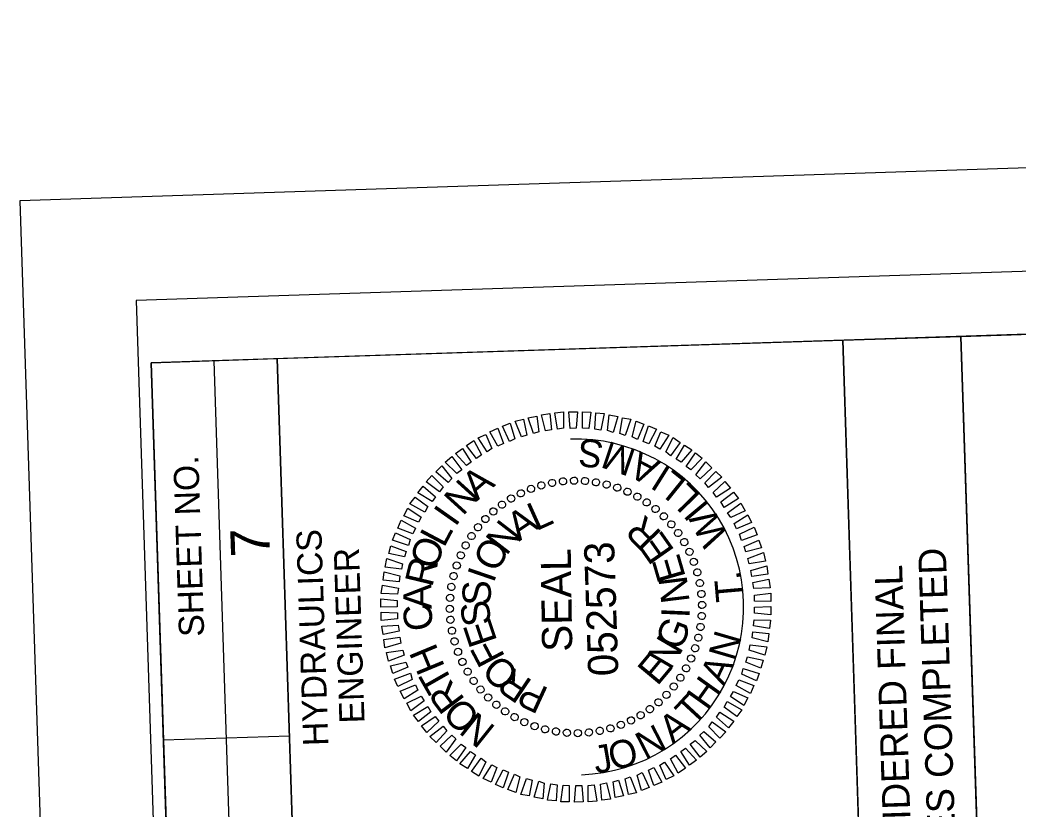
# Model space of a CAD drawing. Extents: x 1627314 to 1628469, y 762309 to 764212.
# Drawn here: x 1627314.2 to 1627512.6, y 763887.6 to 764044.4 of the extents above; entities that cross this region are included whole.
import ezdxf

# ---------------------------------------------------------------- set-up
doc = ezdxf.new("R2010")
doc.units = 0
for name, color, linetype in [('Old_Level_58', 7, 'Continuous'), ('Scratch_Level_0', 7, 'Continuous'), ('Sheet Data Field CELL', 7, 'Continuous'), ('Sheet Plot Border Inside CELL', 7, 'Continuous'), ('Sheet Plot Border Outside CELL', 7, 'Continuous'), ('Sheet Professional Seal CELL', 7, 'Continuous'), ('Sheet Profile CELL', 7, 'Continuous'), ('Sheet Profile Grid Major CELL', 7, 'Continuous'), ('Sheet Profile Grid Minor CELL', 7, 'Continuous'), ('Sheet Sticker Exception Certification CELL', 7, 'Continuous')]:
    doc.layers.add(name, color=color, linetype=linetype)

msp = doc.modelspace()

# ---------------------------------------------------------------- linework, layer by layer
at = {"layer": 'Old_Level_58'}
msp.add_lwpolyline([(1627507.79, 763781.55), (1627501.25, 763981.49), (1627565.16, 763983.58), (1627571.7, 763783.64)], close=True, dxfattribs=at)
at = {"layer": 'Scratch_Level_0'}
msp.add_arc((1627424.73, 763927.73), 33.36, 271.8735, 91.8735, dxfattribs=at)
at = {"layer": 'Sheet Plot Border Inside CELL'}
msp.add_lwpolyline([(1628446.34, 762357.53), (1628391.86, 764023.14), (1627337.33, 763988.65), (1627391.81, 762323.04)], close=True, dxfattribs=at)
at = {"layer": 'Sheet Plot Border Outside CELL'}
msp.add_lwpolyline([(1628469.21, 762345.27), (1628413.63, 764044.37), (1627314.22, 764008.4), (1627369.79, 762309.31)], close=True, dxfattribs=at)
at = {"layer": 'Sheet Professional Seal CELL'}
for p, q in [((1627417.84, 763951.87), (1627417.84, 763951.87)), ((1627420.03, 763952.34), (1627420.03, 763952.34)), ((1627422.17, 763952.71), (1627422.17, 763952.71)), ((1627424.36, 763952.83), (1627424.36, 763952.83)), ((1627426.57, 763952.75), (1627426.57, 763952.75)), ((1627428.73, 763952.48), (1627428.73, 763952.48)), ((1627430.84, 763952.09), (1627430.84, 763952.09)), ((1627432.96, 763951.46), (1627432.96, 763951.46)), ((1627413.79, 763950.34), (1627413.79, 763950.34)), ((1627415.76, 763951.2), (1627415.76, 763951.2)), ((1627434.99, 763950.63), (1627434.99, 763950.63)), ((1627436.97, 763949.69), (1627436.97, 763949.69)), ((1627410.01, 763948.06), (1627410.01, 763948.06)), ((1627411.87, 763949.27), (1627411.87, 763949.27)), ((1627438.81, 763948.5), (1627438.81, 763948.5)), ((1627408.3, 763946.75), (1627408.3, 763946.75)), ((1627440.61, 763947.21), (1627440.61, 763947.21)), ((1627442.2, 763945.76), (1627442.2, 763945.76)), ((1627405.26, 763943.6), (1627405.26, 763943.6)), ((1627406.7, 763945.2), (1627406.7, 763945.2)), ((1627443.76, 763944.16), (1627443.76, 763944.16)), ((1627403.96, 763941.81), (1627403.96, 763941.81)), ((1627445.06, 763942.45), (1627445.06, 763942.45)), ((1627402.77, 763939.97), (1627402.77, 763939.97)), ((1627446.28, 763940.59), (1627446.28, 763940.59)), ((1627401.84, 763937.99), (1627401.84, 763937.99)), ((1627447.34, 763938.68), (1627447.34, 763938.68)), ((1627401, 763935.96), (1627401, 763935.96)), ((1627448.2, 763936.7), (1627448.2, 763936.7)), ((1627400.37, 763933.84), (1627400.37, 763933.84)), ((1627448.87, 763934.62), (1627448.87, 763934.62)), ((1627399.99, 763931.72), (1627399.99, 763931.72)), ((1627449.34, 763932.44), (1627449.34, 763932.44)), ((1627449.71, 763930.3), (1627449.71, 763930.3)), ((1627399.71, 763929.56), (1627399.71, 763929.56)), ((1627424.73, 763927.73), (1627424.73, 763927.73)), ((1627449.84, 763928.1), (1627449.84, 763928.1)), ((1627399.63, 763927.36), (1627399.63, 763927.36)), ((1627449.76, 763925.9), (1627449.76, 763925.9)), ((1627399.76, 763925.16), (1627399.76, 763925.16)), ((1627449.48, 763923.74), (1627449.48, 763923.74)), ((1627400.13, 763923.02), (1627400.13, 763923.02)), ((1627400.6, 763920.84), (1627400.6, 763920.84)), ((1627449.1, 763921.62), (1627449.1, 763921.62)), ((1627401.27, 763918.76), (1627401.27, 763918.76)), ((1627448.47, 763919.5), (1627448.47, 763919.5)), ((1627402.13, 763916.79), (1627402.13, 763916.79)), ((1627447.63, 763917.47), (1627447.63, 763917.47)), ((1627403.19, 763914.87), (1627403.19, 763914.87)), ((1627446.7, 763915.49), (1627446.7, 763915.49)), ((1627404.4, 763913.01), (1627404.4, 763913.01)), ((1627444.21, 763911.86), (1627444.21, 763911.86)), ((1627445.51, 763913.65), (1627445.51, 763913.65)), ((1627405.71, 763911.3), (1627405.71, 763911.3)), ((1627442.77, 763910.26), (1627442.77, 763910.26)), ((1627407.26, 763909.7), (1627407.26, 763909.7)), ((1627408.86, 763908.25), (1627408.86, 763908.25)), ((1627441.17, 763908.71), (1627441.17, 763908.71)), ((1627410.66, 763906.96), (1627410.66, 763906.96)), ((1627437.6, 763906.19), (1627437.6, 763906.19)), ((1627439.46, 763907.4), (1627439.46, 763907.4)), ((1627412.5, 763905.77), (1627412.5, 763905.77)), ((1627414.48, 763904.83), (1627414.48, 763904.83)), ((1627416.51, 763904), (1627416.51, 763904)), ((1627433.71, 763904.26), (1627433.71, 763904.26)), ((1627435.68, 763905.13), (1627435.68, 763905.13)), ((1627418.63, 763903.37), (1627418.63, 763903.37)), ((1627420.74, 763902.99), (1627420.74, 763902.99)), ((1627422.9, 763902.71), (1627422.9, 763902.71)), ((1627425.11, 763902.63), (1627425.11, 763902.63)), ((1627427.3, 763902.75), (1627427.3, 763902.75)), ((1627429.44, 763903.12), (1627429.44, 763903.12)), ((1627431.63, 763903.59), (1627431.63, 763903.59))]:
    msp.add_line(p, q, dxfattribs=at)
for points in [[(1627416.3, 763962.17), (1627415.25, 763965.29), (1627416.94, 763965.65), (1627417.34, 763962.51)], [(1627418.69, 763962.7), (1627417.88, 763965.93), (1627419.58, 763966.13), (1627419.88, 763962.94)], [(1627421.08, 763963.08), (1627420.57, 763966.32), (1627422.27, 763966.47), (1627422.27, 763963.22)], [(1627423.57, 763963.21), (1627423.32, 763966.46), (1627425.02, 763966.51), (1627424.77, 763963.25)], [(1627426.07, 763963.24), (1627426.07, 763966.5), (1627427.72, 763966.45), (1627427.28, 763963.18)], [(1627428.48, 763963.07), (1627428.68, 763966.28), (1627430.38, 763966.14), (1627429.69, 763962.86)], [(1627431.04, 763962.76), (1627431.34, 763965.87), (1627433.05, 763965.57), (1627432.11, 763962.39)], [(1627433.46, 763962.19), (1627434.01, 763965.31), (1627435.67, 763965.01), (1627434.53, 763961.82)], [(1627411.55, 763960.62), (1627410.15, 763963.62), (1627411.68, 763964.22), (1627412.59, 763961.15)], [(1627413.92, 763961.5), (1627412.67, 763964.66), (1627414.31, 763965.01), (1627414.96, 763961.88)], [(1627435.89, 763961.51), (1627436.68, 763964.64), (1627438.25, 763964.04), (1627436.95, 763961)], [(1627438.12, 763960.59), (1627439.17, 763963.72), (1627440.74, 763963.02), (1627439.23, 763960.12)], [(1627407.12, 763958.57), (1627405.28, 763961.31), (1627406.8, 763962.01), (1627408.05, 763959.2)], [(1627409.23, 763959.64), (1627407.64, 763962.54), (1627409.22, 763963.24), (1627410.32, 763960.18)], [(1627440.45, 763959.66), (1627441.61, 763962.55), (1627443.18, 763961.85), (1627441.42, 763959.09)], [(1627442.64, 763958.53), (1627444.04, 763961.38), (1627445.48, 763960.43), (1627443.56, 763957.76)], [(1627404.96, 763957.2), (1627402.97, 763959.79), (1627404.44, 763960.79), (1627405.94, 763957.93)], [(1627444.69, 763957.1), (1627446.3, 763959.85), (1627447.78, 763958.95), (1627445.66, 763956.48)], [(1627401.05, 763954.27), (1627398.73, 763956.5), (1627400.05, 763957.59), (1627402.03, 763955)], [(1627402.95, 763955.83), (1627400.78, 763958.21), (1627402.19, 763959.21), (1627403.88, 763956.47)], [(1627446.63, 763955.66), (1627448.5, 763958.32), (1627449.83, 763957.27), (1627447.56, 763954.99)], [(1627399.31, 763952.46), (1627396.89, 763954.54), (1627398.05, 763955.77), (1627400.09, 763953.24)], [(1627448.59, 763953.98), (1627450.55, 763956.59), (1627451.75, 763955.38), (1627449.41, 763953.2)], [(1627397.62, 763950.61), (1627394.96, 763952.57), (1627396.12, 763953.81), (1627398.34, 763951.58)], [(1627450.39, 763952.38), (1627452.52, 763954.65), (1627453.76, 763953.49), (1627451.12, 763951.46)], [(1627396.14, 763948.66), (1627393.33, 763950.42), (1627394.38, 763951.75), (1627396.8, 763949.63)], [(1627452.01, 763950.44), (1627454.34, 763952.66), (1627455.43, 763951.35), (1627452.69, 763949.51)], [(1627394.7, 763946.56), (1627391.75, 763948.21), (1627392.75, 763949.55), (1627395.27, 763947.68)], [(1627453.57, 763948.59), (1627456.06, 763950.52), (1627457.05, 763949.25), (1627454.2, 763947.51)], [(1627454.89, 763946.43), (1627457.53, 763948.36), (1627458.38, 763946.84), (1627455.52, 763945.5)], [(1627393.42, 763944.57), (1627390.52, 763945.82), (1627391.33, 763947.35), (1627393.99, 763945.54)], [(1627456.16, 763944.32), (1627458.91, 763946.01), (1627459.66, 763944.48), (1627456.64, 763943.23)], [(1627392.34, 763942.23), (1627389.35, 763943.38), (1627390, 763944.96), (1627392.86, 763943.35)], [(1627457.28, 763942.15), (1627460.14, 763943.55), (1627460.79, 763942.07), (1627457.62, 763940.91)], [(1627391.47, 763939.95), (1627388.28, 763941), (1627388.84, 763942.42), (1627391.78, 763941.11)], [(1627390.64, 763937.67), (1627387.52, 763938.32), (1627387.97, 763939.89), (1627390.96, 763938.73)], [(1627458.16, 763939.73), (1627461.12, 763940.98), (1627461.62, 763939.44), (1627458.54, 763938.69)], [(1627458.89, 763937.35), (1627462, 763938.51), (1627462.41, 763936.82), (1627459.17, 763936.31)], [(1627390.07, 763935.25), (1627386.81, 763935.65), (1627387.15, 763937.36), (1627390.29, 763936.31)], [(1627459.52, 763934.97), (1627462.69, 763935.88), (1627462.89, 763934.23), (1627459.71, 763933.78)], [(1627389.6, 763932.69), (1627386.39, 763933.03), (1627386.59, 763934.69), (1627389.71, 763933.89)], [(1627389.28, 763930.27), (1627386.03, 763930.37), (1627386.27, 763932.03), (1627389.44, 763931.48)], [(1627459.89, 763932.58), (1627463.07, 763933.24), (1627463.33, 763931.55), (1627460.08, 763931.39)], [(1627460.23, 763930.09), (1627463.47, 763930.45), (1627463.47, 763928.8), (1627460.22, 763928.89)], [(1627389.21, 763927.77), (1627385.97, 763927.66), (1627385.96, 763929.31), (1627389.22, 763928.97)], [(1627460.25, 763927.69), (1627463.5, 763927.8), (1627463.51, 763926.15), (1627460.24, 763926.49)], [(1627389.24, 763925.37), (1627386, 763925.01), (1627386, 763926.66), (1627389.25, 763926.57)], [(1627389.57, 763922.88), (1627386.39, 763922.23), (1627386.14, 763923.92), (1627389.39, 763924.07)], [(1627460.19, 763925.19), (1627463.44, 763925.1), (1627463.2, 763923.44), (1627460.03, 763923.98)], [(1627389.95, 763920.49), (1627386.78, 763919.59), (1627386.58, 763921.23), (1627389.76, 763921.69)], [(1627459.87, 763922.78), (1627463.08, 763922.43), (1627462.88, 763920.78), (1627459.75, 763921.57)], [(1627459.4, 763920.21), (1627462.66, 763919.82), (1627462.32, 763918.11), (1627459.18, 763919.15)], [(1627390.58, 763918.11), (1627387.47, 763916.96), (1627387.06, 763918.65), (1627390.3, 763919.15)], [(1627458.83, 763917.79), (1627461.95, 763917.14), (1627461.5, 763915.58), (1627458.51, 763916.73)], [(1627391.31, 763915.73), (1627388.35, 763914.49), (1627387.85, 763916.02), (1627390.92, 763916.77)], [(1627392.19, 763913.31), (1627389.33, 763911.92), (1627388.68, 763913.4), (1627391.85, 763914.55)], [(1627458, 763915.51), (1627461.19, 763914.47), (1627460.63, 763913.05), (1627457.69, 763914.35)], [(1627393.31, 763911.15), (1627390.56, 763909.45), (1627389.81, 763910.98), (1627392.82, 763912.23)], [(1627457.13, 763913.23), (1627460.12, 763912.08), (1627459.47, 763910.51), (1627456.61, 763912.12)], [(1627394.58, 763909.04), (1627391.94, 763907.1), (1627391.09, 763908.62), (1627393.95, 763909.97)], [(1627456.05, 763910.9), (1627458.94, 763909.64), (1627458.14, 763908.11), (1627455.48, 763909.93)], [(1627395.9, 763906.88), (1627393.41, 763904.95), (1627392.42, 763906.21), (1627395.27, 763907.96)], [(1627454.77, 763908.9), (1627457.72, 763907.25), (1627456.71, 763905.92), (1627454.2, 763907.78)], [(1627397.46, 763905.03), (1627395.13, 763902.8), (1627394.04, 763904.12), (1627396.78, 763905.96)], [(1627453.33, 763906.81), (1627456.14, 763905.05), (1627455.09, 763903.71), (1627452.67, 763905.83)], [(1627399.08, 763903.08), (1627396.95, 763900.81), (1627395.71, 763901.97), (1627398.35, 763904.01)], [(1627451.85, 763904.86), (1627454.51, 763902.89), (1627453.35, 763901.65), (1627451.13, 763903.88)], [(1627400.88, 763901.49), (1627398.91, 763898.87), (1627397.72, 763900.08), (1627400.05, 763902.26)], [(1627450.16, 763903), (1627452.58, 763900.93), (1627451.42, 763899.69), (1627449.38, 763902.22)], [(1627402.84, 763899.8), (1627400.97, 763897.14), (1627399.64, 763898.2), (1627401.91, 763900.47)], [(1627448.41, 763901.19), (1627450.74, 763898.97), (1627449.42, 763897.87), (1627447.44, 763900.46)], [(1627404.78, 763898.36), (1627403.17, 763895.61), (1627401.69, 763896.51), (1627403.81, 763898.98)], [(1627444.51, 763898.26), (1627446.49, 763895.68), (1627445.03, 763894.68), (1627443.53, 763897.53)], [(1627446.51, 763899.63), (1627448.69, 763897.25), (1627447.28, 763896.25), (1627445.59, 763899)], [(1627406.83, 763896.93), (1627405.42, 763894.08), (1627403.99, 763895.04), (1627405.91, 763897.7)], [(1627409.02, 763895.8), (1627407.86, 763892.91), (1627406.29, 763893.61), (1627408.05, 763896.37)], [(1627442.35, 763896.89), (1627444.19, 763894.15), (1627442.66, 763893.45), (1627441.42, 763896.26)], [(1627411.35, 763894.88), (1627410.3, 763891.74), (1627408.73, 763892.44), (1627410.24, 763895.34)], [(1627413.58, 763893.95), (1627412.78, 763890.82), (1627411.21, 763891.42), (1627412.52, 763894.46)], [(1627435.54, 763893.97), (1627436.8, 763890.81), (1627435.16, 763890.45), (1627434.51, 763893.58)], [(1627437.92, 763894.85), (1627439.32, 763891.84), (1627437.78, 763891.24), (1627436.88, 763894.31)], [(1627440.24, 763895.82), (1627441.83, 763892.92), (1627440.25, 763892.22), (1627439.15, 763895.29)], [(1627416.01, 763893.28), (1627415.46, 763890.16), (1627413.8, 763890.45), (1627414.94, 763893.64)], [(1627418.43, 763892.71), (1627418.13, 763889.6), (1627416.42, 763889.89), (1627417.36, 763893.07)], [(1627420.99, 763892.39), (1627420.79, 763889.18), (1627419.09, 763889.33), (1627419.78, 763892.6)], [(1627423.39, 763892.22), (1627423.4, 763888.97), (1627421.75, 763889.01), (1627422.19, 763892.28)], [(1627425.9, 763892.25), (1627426.15, 763889.01), (1627424.45, 763888.95), (1627424.7, 763892.21)], [(1627428.39, 763892.38), (1627428.9, 763889.15), (1627427.2, 763888.99), (1627427.2, 763892.24)], [(1627430.78, 763892.76), (1627431.59, 763889.54), (1627429.89, 763889.33), (1627429.59, 763892.52)], [(1627433.17, 763893.29), (1627434.22, 763890.17), (1627432.53, 763889.82), (1627432.13, 763892.95)]]:
    msp.add_lwpolyline(points, close=True, dxfattribs=at)
for centre, major_axis in [((1627422.17, 763952.68), (-0.074, 0.716)), ((1627424.35, 763952.81), (-0.011, 0.72)), ((1627426.54, 763952.75), (0.052, 0.718)), ((1627415.8, 763951.17), (-0.257, 0.673)), ((1627417.87, 763951.86), (-0.197, 0.693)), ((1627420, 763952.36), (-0.136, 0.707)), ((1627428.71, 763952.49), (0.114, 0.711)), ((1627430.86, 763952.05), (0.176, 0.698)), ((1627432.95, 763951.43), (0.236, 0.68)), ((1627434.99, 763950.62), (0.294, 0.657)), ((1627411.86, 763949.26), (-0.369, 0.618)), ((1627413.79, 763950.3), (-0.314, 0.648)), ((1627436.94, 763949.64), (0.35, 0.629)), ((1627408.32, 763946.7), (-0.471, 0.544)), ((1627410.04, 763948.05), (-0.422, 0.583)), ((1627438.8, 763948.49), (0.404, 0.596)), ((1627440.56, 763947.19), (0.454, 0.559)), ((1627406.73, 763945.19), (-0.517, 0.501)), ((1627442.2, 763945.73), (0.501, 0.517)), ((1627405.28, 763943.56), (-0.559, 0.454)), ((1627443.7, 763944.14), (0.544, 0.471)), ((1627403.97, 763941.8), (-0.596, 0.404)), ((1627445.06, 763942.43), (0.583, 0.422)), ((1627402.83, 763939.94), (-0.629, 0.35)), ((1627446.26, 763940.6), (0.618, 0.369)), ((1627401.85, 763937.98), (-0.657, 0.294)), ((1627447.3, 763938.68), (0.648, 0.314)), ((1627401.04, 763935.95), (-0.68, 0.236)), ((1627448.17, 763936.67), (0.673, 0.257)), ((1627400.41, 763933.85), (-0.698, 0.176)), ((1627448.86, 763934.59), (0.693, 0.197)), ((1627399.97, 763931.71), (-0.711, 0.114)), ((1627449.36, 763932.46), (0.707, 0.136)), ((1627399.72, 763929.54), (-0.718, 0.052)), ((1627449.68, 763930.3), (0.716, 0.074)), ((1627399.66, 763927.35), (-0.72, -0.011)), ((1627449.81, 763928.11), (0.72, 0.011)), ((1627399.79, 763925.17), (-0.716, -0.074)), ((1627449.75, 763925.93), (0.718, -0.052)), ((1627400.1, 763923), (-0.707, -0.136)), ((1627449.5, 763923.75), (0.711, -0.114)), ((1627400.61, 763920.87), (-0.693, -0.197)), ((1627449.06, 763921.61), (0.698, -0.176)), ((1627448.43, 763919.51), (0.68, -0.236)), ((1627401.3, 763918.8), (-0.673, -0.257)), ((1627447.62, 763917.48), (0.657, -0.294)), ((1627402.17, 763916.79), (-0.648, -0.314)), ((1627446.64, 763915.52), (0.629, -0.35)), ((1627403.21, 763914.86), (-0.618, -0.369)), ((1627404.41, 763913.03), (-0.583, -0.422)), ((1627445.5, 763913.66), (0.596, -0.404)), ((1627405.77, 763911.32), (-0.544, -0.471)), ((1627444.19, 763911.91), (0.559, -0.454)), ((1627407.27, 763909.73), (-0.501, -0.517)), ((1627442.74, 763910.27), (0.517, -0.501)), ((1627408.91, 763908.28), (-0.454, -0.559)), ((1627410.66, 763906.97), (-0.404, -0.596)), ((1627439.43, 763907.41), (0.422, -0.583)), ((1627441.15, 763908.77), (0.471, -0.544)), ((1627412.53, 763905.82), (-0.35, -0.629)), ((1627435.68, 763905.17), (0.314, -0.648)), ((1627437.6, 763906.21), (0.369, -0.618)), ((1627414.48, 763904.84), (-0.294, -0.657)), ((1627416.52, 763904.04), (-0.236, -0.68)), ((1627418.61, 763903.41), (-0.176, -0.698)), ((1627429.47, 763903.1), (0.136, -0.707)), ((1627431.59, 763903.61), (0.197, -0.693)), ((1627433.67, 763904.3), (0.257, -0.673)), ((1627420.76, 763902.97), (-0.114, -0.711)), ((1627422.93, 763902.72), (-0.052, -0.718)), ((1627425.12, 763902.65), (0.011, -0.72)), ((1627427.3, 763902.78), (0.074, -0.716))]:
    msp.add_ellipse(centre, major_axis=major_axis, ratio=0.999708, dxfattribs=at)
at = {"layer": 'Sheet Profile CELL'}
for p, q in [((1627359.37, 763776.71), (1627352.83, 763976.65)), ((1627342.78, 763901.28), (1627367.77, 763902.1))]:
    msp.add_line(p, q, dxfattribs=at)
for points in [[(1627340.28, 763976.24), (1627389.32, 762477.04), (1628438.76, 762511.37), (1628389.72, 764010.57)], [(1627368.59, 763877.11), (1627365.32, 763977.06), (1627477.76, 763980.74), (1627481.03, 763880.79)], [(1627346.82, 763776.3), (1627340.28, 763976.24), (1627365.32, 763977.06), (1627371.86, 763777.12)]]:
    msp.add_lwpolyline(points, close=True, dxfattribs=at)
at = {"layer": 'Sheet Profile Grid Major CELL'}
msp.add_lwpolyline([(1627566.8, 763933.62), (1627841.65, 763942.61), (1627840.02, 763992.59), (1627490.2, 763981.14)], dxfattribs=at)
at = {"layer": 'Sheet Sticker Exception Certification CELL'}
for p, q in [((1627477.77, 763980.72), (1627501.26, 763981.49)), ((1627477.77, 763980.72), (1627501.26, 763981.49)), ((1627501.25, 763981.49), (1627507.79, 763781.56)), ((1627501.25, 763981.49), (1627507.79, 763781.56)), ((1627484.3, 763780.79), (1627477.76, 763980.72)), ((1627484.3, 763780.79), (1627477.76, 763980.72))]:
    msp.add_line(p, q, dxfattribs=at)

# ---------------------------------------------------------------- texts
at = {"layer": 'Old_Level_58'}
for s, rotation, p in [('S', 173.0617, (1627430.44, 763960.65)), ('M', 161.4413, (1627436.96, 763958.82)), ('A', 152.311, (1627441.74, 763956.49)), ('I', 147.846, (1627443.92, 763955.08)), ('L', 141.0913, (1627447.01, 763952.63)), ('L', 134.3366, (1627449.78, 763949.84)), ('I', 129.8716, (1627451.43, 763947.82)), ('W', 117.321, (1627455.15, 763941.54)), ('.', 102.2517, (1627457.7, 763933.16)), ('T', 95.0104, (1627458.12, 763928.96)), ('N', 73.7445, (1627456.29, 763916.77)), ('A', 64.6142, (1627454.15, 763911.9)), ('H', 54.4249, (1627450.89, 763906.94)), ('T', 47.1836, (1627448.06, 763903.81)), ('A', 38.0533, (1627443.97, 763900.42)), ('N', 27.1771, (1627438.47, 763897.28)), ('J', 9.715, (1627428.7, 763894.56)), ('O', 15.528, (1627432.04, 763895.13))]:
    msp.add_text(s, height=5.5, rotation=rotation, dxfattribs=at).set_placement(p)
at = {"layer": 'Sheet Data Field CELL'}
msp.add_text('7', height=7.75, rotation=91.8735, dxfattribs=at).set_placement((1627363.94, 763937.74))
at = {"layer": 'Sheet Professional Seal CELL'}
for s, height, rotation, p in [('A', 5.64, 40.4906, (1627405.09, 763948.7)), ('N', 5.64, 47.6924, (1627402.24, 763945.66)), ('I', 5.64, 54.8936, (1627400.76, 763943.46)), ('L', 5.64, 24.2743, (1627416.79, 763942.73)), ('A', 5.64, 33.6337, (1627413.41, 763940.67)), ('R', 5.64, 134.3549, (1627442.01, 763942.4)), ('N', 5.64, 52.3501, (1627410.9, 763937.73)), ('L', 5.64, 62.0943, (1627398.49, 763939.33)), ('E', 5.64, 124.9976, (1627444.48, 763938.93)), ('O', 5.64, 69.2946, (1627396.79, 763934.87)), ('O', 5.64, 61.707, (1627409.01, 763934.32)), ('SEAL', 5.998, 90.8735, (1627424.02, 763918.85)), ('E', 5.64, 106.2852, (1627446.6, 763933.7)), ('R', 5.64, 76.4946, (1627396.15, 763931.5)), ('I', 5.64, 71.0631, (1627408.38, 763932.3)), ('N', 5.64, 96.9299, (1627447.36, 763928.77)), ('A', 5.64, 90.8938, (1627396.08, 763927.29)), ('S', 5.64, 89.7739, (1627407.82, 763927.98)), ('C', 5.64, 98.0933, (1627396.51, 763923.36)), ('S', 5.64, 99.1291, (1627407.99, 763924.38)), ('I', 5.64, 87.5747, (1627447.32, 763925.42)), ('E', 5.64, 108.4845, (1627409.15, 763920.97)), ('G', 5.64, 68.8637, (1627445.64, 763918.81)), ('N', 5.64, 59.5074, (1627443.51, 763914.94)), ('H', 5.64, 112.4929, (1627398.76, 763915.83)), ('F', 5.64, 117.8405, (1627410.75, 763917.82)), ('E', 5.64, 50.1504, (1627440.91, 763911.85)), ('O', 5.64, 136.5547, (1627413.81, 763914.62)), ('R', 5.64, 145.9131, (1627416.31, 763912.95)), ('T', 5.64, 119.6932, (1627400.52, 763912.63)), ('R', 5.64, 126.894, (1627402.83, 763909.31)), ('P', 5.64, 155.2724, (1627419.56, 763911.45)), ('O', 5.64, 134.0952, (1627406.04, 763905.96)), ('N', 5.64, 141.297, (1627409.01, 763903.75))]:
    msp.add_text(s, height=height, rotation=rotation, dxfattribs=at).set_placement(p)
at = {"layer": 'Sheet Profile CELL'}
for s, p in [('SHEET NO.', (1627350.85, 763921.87)), ('HYDRAULICS', (1627375.53, 763900.16)), ('ENGINEER', (1627382.73, 763904.65))]:
    msp.add_text(s, height=5, rotation=91.8735, dxfattribs=at).set_placement(p)
at = {"layer": 'Sheet Profile Grid Minor CELL'}
msp.add_text('052573', height=5.998, rotation=91.8735, dxfattribs=at).set_placement((1627433.19, 763914.05))
at = {"layer": 'Sheet Sticker Exception Certification CELL'}
for s, p in [('UNLESS ALL SIGNATURES COMPLETED', (1627502.91, 763797.41)), ('UNLESS ALL SIGNATURES COMPLETED', (1627502.91, 763797.41)), ('DOCUMENT NOT CONSIDERED FINAL', (1627493.95, 763802.19)), ('DOCUMENT NOT CONSIDERED FINAL', (1627493.95, 763802.19))]:
    msp.add_text(s, height=5.5, rotation=91.8735, dxfattribs=at).set_placement(p)

doc.saveas('drawing.dxf')
